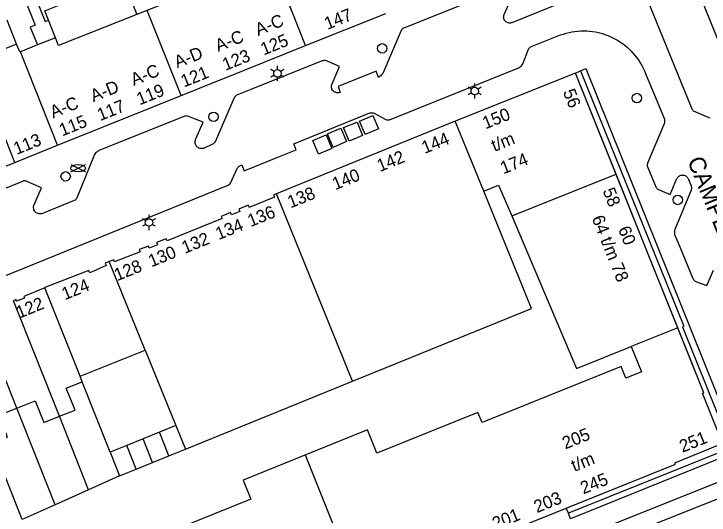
# Model space of a CAD drawing. Extents: x 122462 to 123306, y 485548 to 486417.
# Drawn here: x 122667.6 to 122750.6, y 485578.6 to 485638.3 of the extents above; entities that cross this region are included whole.
import ezdxf

# ---------------------------------------------------------------- set-up
doc = ezdxf.new("R2010")
doc.units = 0
for name, color, linetype in [('Level 1', 7, 'Continuous'), ('Level 10', 7, 'Continuous'), ('Level 11', 7, 'Continuous'), ('Level 17', 7, 'Continuous'), ('Level 19', 7, 'Continuous'), ('Level 22', 7, 'Continuous'), ('Level 23', 7, 'Continuous'), ('Level 4', 7, 'Continuous'), ('Level 42', 7, 'Continuous'), ('Level 5', 7, 'Continuous'), ('Level 50', 7, 'Continuous'), ('Level 52', 7, 'Continuous'), ('Level 53', 7, 'Continuous'), ('Level 58', 7, 'Continuous'), ('Level 59', 7, 'Continuous')]:
    doc.layers.add(name, color=color, linetype=linetype)

msp = doc.modelspace()

# ---------------------------------------------------------------- linework, layer by layer
at = {"layer": 'Level 1'}
for p, q in [((122702.39, 485634.579), (122711.979, 485638.41)), ((122672.529, 485635.494), (122670.367, 485634.635)), ((122667.884, 485634.745), (122662.842, 485632.728)), ((122670.367, 485634.635), (122668.352, 485633.836)), ((122667.689, 485620.61), (122672.778, 485622.687)), ((122662.818, 485618.661), (122667.689, 485620.61)), ((122675.461, 485595.11), (122683.253, 485598.212)), ((122683.253, 485598.212), (122686.898, 485589.237)), ((122675.729, 485594.437), (122675.461, 485595.11)), ((122688.038, 485586.43), (122707.986, 485594.532)), ((122686.898, 485589.237), (122684.959, 485588.449)), ((122684.959, 485588.449), (122682.995, 485587.651)), ((122682.995, 485587.651), (122681.03, 485586.853)), ((122681.03, 485586.853), (122679.066, 485586.055)), ((122686.079, 485585.634), (122688.038, 485586.43)), ((122679.066, 485586.055), (122680.186, 485583.24)), ((122684.115, 485584.836), (122686.079, 485585.634)), ((122682.15, 485584.038), (122684.115, 485584.836)), ((122680.186, 485583.24), (122682.15, 485584.038))]:
    msp.add_line(p, q, dxfattribs=at)
for points in [[(122693.839, 485643.954), (122693.655, 485643.881), (122694.024, 485642.952), (122682.238, 485638.273)], [(122682.238, 485638.273), (122672.898, 485634.565), (122672.529, 485635.494)], [(122668.352, 485633.836), (122668.26, 485633.799), (122667.884, 485634.745)], [(122672.778, 485622.687), (122694.966, 485631.598), (122702.39, 485634.579)], [(122739.45, 485619.223), (122734.602, 485631.285), (122720.259, 485625.549)], [(122720.259, 485625.549), (122700.534, 485617.539), (122698.91, 485616.879)], [(122746.809, 485600.912), (122743.13, 485610.068), (122739.45, 485619.223)], [(122723.648, 485617.213), (122725.423, 485617.923), (122726.987, 485614.24)], [(122698.91, 485616.879), (122698.571, 485616.741), (122698.681, 485616.481), (122695.641, 485615.251), (122695.531, 485615.511), (122694.421, 485615.051), (122694.537, 485614.771), (122693.535, 485614.36), (122693.421, 485614.641), (122692.311, 485614.191), (122692.411, 485613.941), (122685.851, 485611.271), (122685.751, 485611.521), (122684.601, 485611.061), (122684.709, 485610.802), (122683.724, 485610.389), (122683.621, 485610.651), (122682.521, 485610.221), (122682.621, 485609.971), (122679.591, 485608.751), (122679.488, 485609), (122678.957, 485608.786)], [(122707.986, 485594.532), (122729.338, 485603.205), (122723.648, 485617.213)], [(122726.987, 485614.24), (122734.714, 485596.044), (122741.239, 485598.67)], [(122678.957, 485608.786), (122678.471, 485608.591), (122678.574, 485608.333), (122676.615, 485607.464), (122676.501, 485607.721), (122671.249, 485605.699), (122671.267, 485605.663)], [(122671.267, 485605.663), (122668.741, 485604.621), (122668.816, 485604.429), (122667.894, 485604.065), (122667.822, 485604.258), (122667.508, 485604.13)], [(122668.059, 485555.746), (122668.934, 485553.565), (122669.34, 485553.735), (122669.402, 485553.584), (122709.518, 485569.732), (122746.524, 485584.628), (122746.453, 485584.804), (122751.715, 485586.922), (122751.998, 485587.535), (122749.768, 485593.083), (122749.93, 485593.148), (122746.809, 485600.912)], [(122741.239, 485598.67), (122742.465, 485595.624), (122740.61, 485594.877), (122740.05, 485596.268), (122723.446, 485589.584), (122722.966, 485590.776), (122710.906, 485585.922), (122709.786, 485588.705), (122694.943, 485582.73), (122695.859, 485580.456), (122663.389, 485567.386), (122668.059, 485555.746)], [(122673.002, 485590.337), (122674.861, 485591.076), (122673.825, 485593.679), (122675.729, 485594.437)], [(122667.916, 485591.327), (122670.108, 485592.199), (122671.145, 485589.596), (122673.002, 485590.337)], [(122664.936, 485587.126), (122666.785, 485587.861), (122665.749, 485590.464), (122667.916, 485591.327)]]:
    msp.add_lwpolyline(points, dxfattribs=at)
at = {"layer": 'Level 10'}
for points in [[(122733.752, 485578.78), (122733.507, 485579.388), (122746.524, 485584.628), (122746.453, 485584.804), (122751.715, 485586.922), (122751.998, 485587.535), (122749.768, 485593.083), (122749.93, 485593.148), (122734.602, 485631.285), (122735.205, 485631.554)], [(122735.205, 485631.554), (122747.527, 485601.085), (122747.387, 485601.031), (122753.182, 485586.597), (122733.752, 485578.78)]]:
    msp.add_lwpolyline(points, dxfattribs=at)
at = {"layer": 'Level 11'}
msp.add_lwpolyline([(122735.205, 485631.554), (122735.828, 485631.825), (122754.183, 485586.26), (122734.001, 485578.115), (122733.752, 485578.78)], dxfattribs=at)
at = {"layer": 'Level 17'}
for points in [[(122670.946, 485548.322), (122692.668, 485557.016), (122711.424, 485564.491), (122754.653, 485581.721), (122773.715, 485590.032), (122813.302, 485605.918), (122824.153, 485610.272), (122875, 485630.623), (122903.898, 485642.235), (122948.388, 485660.097), (122952.679, 485661.82), (122986.651, 485675.409), (122987.53, 485675.801), (122987.613, 485675.825), (122987.699, 485675.835), (122987.785, 485675.83), (122987.869, 485675.811), (122987.949, 485675.777), (122988.022, 485675.731), (122988.086, 485675.673), (122988.139, 485675.605), (122988.18, 485675.529), (122988.742, 485674.122), (122988.768, 485674.042)], [(122739.792, 485648.43), (122748.504, 485627.024), (122748.547, 485626.938), (122748.603, 485626.86), (122748.67, 485626.793), (122748.748, 485626.737), (122748.834, 485626.694), (122750.538, 485626.002), (122750.636, 485625.934)], [(122724.857, 485640.975), (122714.176, 485636.691), (122714.079, 485636.646), (122713.99, 485636.588), (122713.91, 485636.517), (122713.842, 485636.436), (122713.786, 485636.345), (122711.607, 485631.245), (122711.538, 485631.147), (122711.461, 485631.056), (122711.375, 485630.972), (122711.282, 485630.896), (122711.182, 485630.83), (122711.077, 485630.773), (122710.811, 485631.531), (122706.266, 485629.679), (122706.524, 485628.984), (122706.448, 485628.947), (122706.367, 485628.923), (122706.283, 485628.911), (122706.198, 485628.911), (122706.115, 485628.925), (122706.034, 485628.952), (122705.959, 485628.99), (122705.869, 485629.021), (122705.785, 485629.065), (122705.708, 485629.121)], [(122734.954, 485640.535), (122726.998, 485637.288), (122726.897, 485637.261), (122726.792, 485637.248), (122726.688, 485637.251), (122726.584, 485637.268), (122726.484, 485637.3), (122726.39, 485637.347), (122726.303, 485637.406), (122726.226, 485637.477), (122726.16, 485637.558), (122726.106, 485637.648), (122726.065, 485637.745), (122726.039, 485637.847), (122726.028, 485637.951), (122726.032, 485638.056), (122726.051, 485638.159), (122726.084, 485638.259), (122727.013, 485640.389)], [(122633.077, 485593.54), (122692.946, 485617.824), (122693.052, 485617.864), (122693.153, 485617.915), (122693.247, 485617.978), (122693.333, 485618.051), (122693.41, 485618.134), (122694.229, 485619.912), (122694.276, 485619.992), (122694.331, 485620.065), (122694.396, 485620.131), (122694.468, 485620.188), (122694.547, 485620.236), (122694.762, 485620.33), (122695.073, 485619.631), (122699.062, 485621.256), (122701.246, 485622.145), (122700.996, 485622.859), (122710.057, 485626.532), (122710.157, 485626.553), (122710.259, 485626.558), (122710.36, 485626.548), (122710.459, 485626.522), (122710.553, 485626.482), (122711.889, 485625.774), (122711.97, 485625.737), (122712.056, 485625.71), (122712.144, 485625.693), (122712.233, 485625.688), (122712.322, 485625.694), (122712.41, 485625.711), (122727.939, 485631.965), (122728.05, 485632.058), (122728.152, 485632.161), (122728.245, 485632.273), (122728.326, 485632.393), (122729.01, 485634.146), (122729.054, 485634.228), (122729.109, 485634.302), (122729.176, 485634.367), (122729.251, 485634.421), (122729.335, 485634.462), (122729.423, 485634.49), (122732.829, 485635.827), (122733.162, 485635.941), (122733.5, 485636.041), (122733.843, 485636.125), (122734.188, 485636.194), (122734.537, 485636.247), (122734.887, 485636.285), (122735.239, 485636.308), (122735.591, 485636.314), (122735.943, 485636.305), (122736.295, 485636.28), (122736.645, 485636.24), (122736.993, 485636.184), (122737.338, 485636.113), (122737.68, 485636.026), (122738.017, 485635.925), (122738.35, 485635.808), (122738.677, 485635.677), (122738.998, 485635.531), (122739.312, 485635.371), (122739.618, 485635.198), (122739.917, 485635.011)], [(122739.917, 485635.011), (122740.207, 485634.811), (122740.488, 485634.598), (122740.759, 485634.372), (122741.02, 485634.135), (122741.27, 485633.887), (122741.509, 485633.628), (122741.735, 485633.358), (122741.95, 485633.079), (122742.152, 485632.79), (122742.341, 485632.493), (122742.517, 485632.187), (122742.679, 485631.874), (122742.827, 485631.554), (122742.96, 485631.228), (122745.218, 485625.766), (122745.24, 485625.657), (122745.248, 485625.546), (122745.242, 485625.435), (122745.222, 485625.326), (122745.189, 485625.22), (122743.209, 485620.539), (122743.185, 485620.439), (122743.175, 485620.336), (122743.178, 485620.233), (122743.195, 485620.131), (122743.225, 485620.032), (122744.199, 485617.7), (122744.242, 485617.616), (122744.297, 485617.54), (122744.364, 485617.474), (122744.44, 485617.419), (122744.524, 485617.377), (122745.901, 485616.808), (122746.716, 485618.693), (122746.766, 485618.784), (122746.828, 485618.866), (122746.901, 485618.939), (122746.984, 485619.001), (122747.075, 485619.051), (122747.172, 485619.087), (122747.272, 485619.11), (122747.376, 485619.118), (122747.479, 485619.111), (122747.58, 485619.09), (122747.677, 485619.055), (122747.769, 485619.007), (122747.852, 485618.946), (122747.926, 485618.874), (122747.99, 485618.792), (122748.041, 485618.702), (122748.079, 485618.606), (122748.398, 485617.831), (122748.427, 485617.747), (122748.445, 485617.66), (122748.453, 485617.572), (122748.448, 485617.483), (122748.433, 485617.396), (122748.407, 485617.311), (122746.458, 485612.614), (122746.432, 485612.47), (122746.42, 485612.324), (122746.423, 485612.177), (122746.441, 485612.032), (122746.856, 485611.031), (122748.611, 485606.793), (122748.659, 485606.697), (122748.719, 485606.609), (122748.792, 485606.531), (122748.875, 485606.464), (122748.967, 485606.41), (122749.066, 485606.369), (122750.288, 485605.96), (122751.076, 485607.79)], [(122705.708, 485629.121), (122705.64, 485629.187), (122705.581, 485629.262), (122705.535, 485629.345), (122705.501, 485629.434), (122705.48, 485629.527), (122705.473, 485629.622), (122705.479, 485629.717), (122705.499, 485629.81), (122705.532, 485629.899), (122705.578, 485629.982), (122706.421, 485632.076), (122704.877, 485632.744), (122704.779, 485632.766), (122704.68, 485632.776), (122704.58, 485632.775), (122704.48, 485632.762), (122704.383, 485632.738), (122695.866, 485629.325), (122694.246, 485628.676), (122694.152, 485628.631), (122694.064, 485628.574), (122693.985, 485628.506), (122693.915, 485628.428), (122693.856, 485628.342), (122693.808, 485628.249), (122691.625, 485623.146), (122691.558, 485623.049), (122691.481, 485622.96), (122691.392, 485622.882), (122691.295, 485622.815), (122691.191, 485622.76), (122690.285, 485622.338), (122690.183, 485622.301), (122690.078, 485622.28), (122689.97, 485622.273), (122689.862, 485622.281), (122689.756, 485622.304), (122689.655, 485622.341), (122689.56, 485622.392), (122689.473, 485622.456), (122689.396, 485622.532), (122689.33, 485622.617), (122689.276, 485622.711), (122689.237, 485622.812), (122689.211, 485622.917), (122689.201, 485623.024), (122689.205, 485623.132), (122689.225, 485623.239), (122689.259, 485623.341), (122690.163, 485625.43), (122688.411, 485626.122), (122688.303, 485626.151), (122688.193, 485626.165), (122688.081, 485626.163), (122687.971, 485626.145), (122687.865, 485626.112), (122677.638, 485622.005), (122677.574, 485621.942), (122677.502, 485621.888), (122677.424, 485621.843), (122677.34, 485621.81), (122677.207, 485621.589), (122675.122, 485616.466), (122675.076, 485616.371), (122675.017, 485616.283), (122674.945, 485616.206), (122674.863, 485616.139), (122674.772, 485616.086), (122670.975, 485614.541), (122670.87, 485614.506), (122670.761, 485614.486), (122670.65, 485614.482), (122670.54, 485614.494), (122670.433, 485614.522), (122670.33, 485614.564), (122670.235, 485614.621), (122670.149, 485614.691), (122670.074, 485614.773), (122670.012, 485614.864), (122669.963, 485614.964), (122669.928, 485615.069), (122669.91, 485615.178), (122669.907, 485615.289), (122669.919, 485615.399), (122669.948, 485615.506), (122670.862, 485617.595), (122669.037, 485618.4), (122668.961, 485618.422), (122668.883, 485618.431), (122668.804, 485618.427), (122668.727, 485618.41), (122668.654, 485618.381), (122668.587, 485618.34), (122657.798, 485614.02)], [(122758.639, 485585.43), (122753.861, 485583.347), (122723.192, 485571.115), (122710.807, 485566.186), (122692.505, 485558.901), (122666.01, 485548.322)]]:
    msp.add_lwpolyline(points, dxfattribs=at)
at = {"layer": 'Level 19'}
for p, q in [((122667.884, 485634.745), (122666.746, 485637.588)), ((122679.066, 485586.055), (122675.729, 485594.437)), ((122672.506, 485579.797), (122667.916, 485591.327)), ((122676.487, 485581.581), (122673.002, 485590.337)), ((122668.558, 485578.027), (122664.936, 485587.126)), ((122680.186, 485583.24), (122676.487, 485581.581)), ((122676.487, 485581.581), (122672.506, 485579.797)), ((122672.506, 485579.797), (122668.558, 485578.027))]:
    msp.add_line(p, q, dxfattribs=at)
for points in [[(122675.803, 485662.392), (122676.141, 485661.543), (122676.442, 485661.663), (122682.099, 485647.412), (122669.514, 485642.417), (122669.416, 485642.664), (122667.268, 485641.812), (122668.122, 485639.66), (122668.91, 485639.973), (122670.094, 485636.991), (122669.52, 485636.763), (122670.367, 485634.635)], [(122693.839, 485643.954), (122692.963, 485646.165), (122693.531, 485646.39), (122690.044, 485655.174), (122681.765, 485651.888), (122683.799, 485646.764), (122669.99, 485641.283), (122670.292, 485640.523), (122670.099, 485640.446), (122671.293, 485637.444), (122671.692, 485637.603)]]:
    msp.add_lwpolyline(points, dxfattribs=at)
at = {"layer": 'Level 22'}
msp.add_line((122754.919, 485627.028), (122743.749, 485654.76), dxfattribs=at)
at = {"layer": 'Level 23'}
msp.add_line((122672.529, 485635.494), (122671.692, 485637.603), dxfattribs=at)
msp.add_lwpolyline([(122671.692, 485637.603), (122671.254, 485638.707), (122673.453, 485639.58), (122672.82, 485641.175), (122679.961, 485644.009), (122682.238, 485638.273)], dxfattribs=at)
at = {"layer": 'Level 4'}
for p, q in [((122702.39, 485634.579), (122697.988, 485645.602)), ((122672.778, 485622.687), (122668.352, 485633.836)), ((122667.689, 485620.61), (122662.842, 485632.728)), ((122723.648, 485617.213), (122720.259, 485625.549)), ((122726.987, 485614.24), (122739.45, 485619.223)), ((122707.986, 485594.532), (122698.91, 485616.879)), ((122683.253, 485598.212), (122678.957, 485608.786)), ((122675.461, 485595.11), (122671.267, 485605.663)), ((122673.002, 485590.337), (122667.508, 485604.13)), ((122667.916, 485591.327), (122663.459, 485602.525)), ((122746.809, 485600.912), (122741.239, 485598.67)), ((122686.898, 485589.237), (122688.038, 485586.43)), ((122686.079, 485585.634), (122684.959, 485588.449)), ((122684.115, 485584.836), (122682.995, 485587.651)), ((122682.15, 485584.038), (122681.03, 485586.853))]:
    msp.add_line(p, q, dxfattribs=at)
at = {"layer": 'Level 42'}
for points in [[(122709.479, 485623.94), (122708.805, 485625.554), (122710.419, 485626.228), (122711.093, 485624.614), (122709.479, 485623.94)], [(122707.588, 485623.172), (122706.924, 485624.778), (122708.53, 485625.442), (122709.194, 485623.836), (122707.588, 485623.172)], [(122705.691, 485622.423), (122705.01, 485624.02), (122706.607, 485624.701), (122707.288, 485623.104), (122705.691, 485622.423)], [(122703.921, 485621.626), (122703.253, 485623.234), (122704.861, 485623.902), (122705.529, 485622.294), (122703.921, 485621.626)]]:
    msp.add_lwpolyline(points, dxfattribs=at)
at = {"layer": 'Level 5'}
for p, q in [((122687.542, 485628.617), (122683.468, 485638.761)), ((122708.899, 485569.483), (122702.364, 485585.717))]:
    msp.add_line(p, q, dxfattribs=at)
at = {"layer": 'Level 50'}
for p, q in [((122699.026, 485631.695), (122699.026, 485632.145)), ((122698.636, 485631.47), (122698.246, 485631.695)), ((122698.636, 485631.02), (122698.246, 485630.795)), ((122699.805, 485631.695), (122699.415, 485631.47)), ((122699.805, 485630.795), (122699.415, 485631.02)), ((122699.026, 485630.345), (122699.026, 485630.795)), ((122722.194, 485629.368), (122721.804, 485629.593)), ((122722.584, 485629.593), (122722.584, 485630.043)), ((122723.363, 485629.593), (122722.973, 485629.368)), ((122722.194, 485628.918), (122721.804, 485628.693)), ((122722.584, 485628.243), (122722.584, 485628.693)), ((122723.363, 485628.693), (122722.973, 485628.918)), ((122683.699, 485613.911), (122683.699, 485614.361)), ((122683.309, 485613.686), (122682.919, 485613.911)), ((122684.478, 485613.911), (122684.088, 485613.686)), ((122683.309, 485613.236), (122682.919, 485613.011)), ((122683.699, 485612.561), (122683.699, 485613.011)), ((122684.478, 485613.011), (122684.088, 485613.236))]:
    msp.add_line(p, q, dxfattribs=at)
for centre in [(122699.026, 485631.245), (122722.584, 485629.143), (122683.699, 485613.461)]:
    msp.add_circle(centre, 0.45, dxfattribs=at)
at = {"layer": 'Level 52'}
for p, q in [((122674.343, 485619.49), (122676.124, 485620.38)), ((122674.343, 485620.38), (122676.124, 485619.49))]:
    msp.add_line(p, q, dxfattribs=at)
msp.add_ellipse((122675.233, 485619.933), major_axis=(0.89, 0), ratio=0.5, dxfattribs=at)
at = {"layer": 'Level 53'}
for centre in [(122711.531, 485634.234), (122741.941, 485628.308), (122691.409, 485626.065), (122673.747, 485618.964), (122746.807, 485616.145)]:
    msp.add_circle(centre, 0.56, dxfattribs=at)

# ---------------------------------------------------------------- texts
at = {"layer": 'Level 58'}
for s, rotation, p in [('147', 21.77669, (122704.984, 485636.426)), ('A-C', 21.88851, (122696.719, 485635.708)), ('A-C', 21.88252, (122691.951, 485633.794)), ('125', 21.88851, (122697.374, 485633.374)), ('A-D', 21.88252, (122687.064, 485631.831)), ('123', 21.88252, (122692.811, 485631.541)), ('A-C', 21.88252, (122681.872, 485629.746)), ('121', 21.88252, (122687.856, 485629.551)), ('A-D', 21.88252, (122677.053, 485627.81)), ('119', 21.88252, (122682.571, 485627.428)), ('56', 291.89409, (122733.079, 485629.044)), ('A-C', 21.88252, (122672.235, 485625.875)), ('117', 21.88252, (122677.867, 485625.539)), ('150', 21.79532, (122723.851, 485624.563)), ('115', 21.88252, (122673.331, 485623.718)), ('113', 21.88252, (122667.879, 485621.511)), ('144', 22.1052, (122716.602, 485621.636)), ('t/m', 21.79532, (122724.923, 485621.88)), ('142', 22.1052, (122711.263, 485619.468)), ('174', 21.79532, (122725.997, 485619.197)), ('140', 22.1052, (122705.926, 485617.301)), ('138', 22.1052, (122700.588, 485615.133)), ('58', 291.88252, (122737.817, 485617.255)), ('136', 22.07763, (122695.825, 485612.897)), ('134', 22.07763, (122691.998, 485611.347)), ('64 t/m 78', 291.89341, (122736.516, 485613.971)), ('60', 291.87295, (122739.657, 485612.679)), ('132', 22.07763, (122687.961, 485609.712)), ('130', 22.07763, (122683.983, 485608.101)), ('128', 22.07763, (122679.891, 485606.444)), ('124', 22.00929, (122673.637, 485604.172)), ('122', 22.41663, (122668.202, 485601.965)), ('205', 21.92873, (122733.384, 485586.38)), ('251', 21.90679, (122747.372, 485585.982)), ('t/m', 21.92873, (122734.46, 485583.697)), ('245', 21.92873, (122735.542, 485581.017)), ('203', 21.92922, (122730.002, 485578.786)), ('201', 21.93599, (122725.035, 485576.786))]:
    msp.add_text(s, height=1.5, rotation=rotation, dxfattribs=at).set_placement(p)
at = {"layer": 'Level 59'}
msp.add_text('CAMPERSTRAAT', height=2, rotation=292.3047, dxfattribs=at).set_placement((122747.922, 485620.842))

doc.saveas('drawing.dxf')
